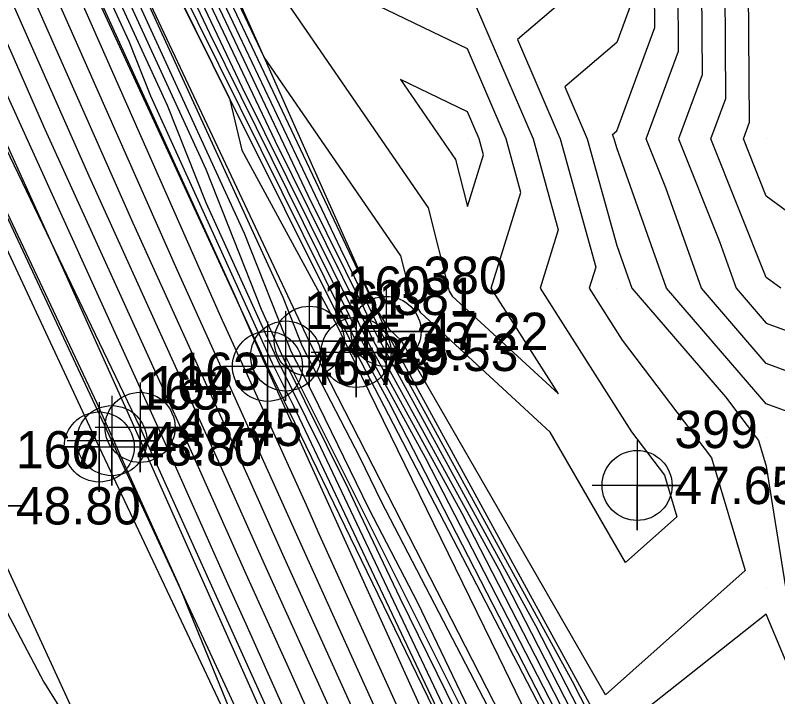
# Model space of a CAD drawing. Extents: x 2090860 to 2091277, y 159470 to 160080.
# Drawn here: x 2091119.7 to 2091170.8, y 159632.7 to 159678.3 of the extents above; entities that cross this region are included whole.
import ezdxf

# ---------------------------------------------------------------- set-up
doc = ezdxf.new("R2010")
doc.units = 0
for name, color, linetype in [('DTM Contours Major', 7, 'Continuous'), ('DTM Contours Minor', 7, 'Continuous'), ('Exist DTM Breakline', 7, 'Continuous'), ('Exist DTM Breakline Cogo Elevation', 7, 'Continuous'), ('Exist DTM Breakline Cogo Number', 7, 'Continuous'), ('Exist DTM Breakline Cogo Point CELL', 7, 'Continuous'), ('Exist DTM Crownline', 7, 'Continuous'), ('Exist DTM Crownline Cogo Elevation', 7, 'Continuous'), ('Exist DTM Crownline Cogo Number', 7, 'Continuous'), ('Exist DTM Crownline Cogo Point CELL', 7, 'Continuous'), ('Exist DTM QL2 LIDAR Elevation Point', 7, 'Continuous'), ('Exist DTM Regular Point CELL', 7, 'Continuous'), ('Exist DTM Regular Point Cogo Elevation', 7, 'Continuous'), ('Exist DTM Regular Point Cogo Number', 7, 'Continuous'), ('Exist Roads EOP', 7, 'Continuous'), ('Exist Roads EOP Cogo Elevation', 7, 'Continuous'), ('Exist Roads EOP Cogo Number', 7, 'Continuous'), ('Exist Roads EOP Cogo Point CELL', 7, 'Continuous'), ('Exist Roads EOT', 7, 'Continuous'), ('Exist Roads EOT Cogo Elevation', 7, 'Continuous'), ('Exist Roads EOT Cogo Number', 7, 'Continuous'), ('Exist Roads EOT Cogo Point CELL', 7, 'Continuous')]:
    doc.layers.add(name, color=color, linetype=linetype)

msp = doc.modelspace()

# ---------------------------------------------------------------- linework, layer by layer
at = {"layer": 'DTM Contours Major'}
for points in [[(2091113.978, 159781.196), (2091107.95, 159774.542), (2091109.45, 159770.226), (2091108.284, 159761.501), (2091106.966, 159748.316), (2091108.177, 159744.971), (2091106.747, 159743.886), (2091107.873, 159737.592), (2091109.304, 159732.696), (2091114.431, 159718.45), (2091115.247, 159716.067), (2091116.563, 159712.414), (2091119.92, 159704.896), (2091128.935, 159685.065), (2091128.953, 159685.024), (2091132.725, 159677.067), (2091142.133, 159658.086), (2091142.373, 159657.575), (2091143.105, 159656.097), (2091147.178, 159648.664), (2091157.027, 159629.517), (2091160.822, 159622.14), (2091162.224, 159619.585), (2091172.872, 159598.824)], [(2091172.606, 159609.793), (2091167.266, 159614.052), (2091165.877, 159617.077), (2091164.245, 159620.259), (2091159.237, 159629.383), (2091158.623, 159630.578), (2091157.028, 159633.678), (2091144.289, 159656.927), (2091144.155, 159657.198), (2091143.409, 159658.787), (2091141.517, 159662.605), (2091130.506, 159685.833), (2091130.452, 159685.953), (2091126.87, 159693.834)], [(2091171.958, 159584.503), (2091159.156, 159611.268), (2091158.366, 159612.924), (2091155.978, 159617.917), (2091145.488, 159639.267), (2091142.826, 159644.878), (2091142.03, 159646.557), (2091137.674, 159655.374), (2091136.215, 159658.575), (2091132.508, 159667.94), (2091125.612, 159682.971)], [(2091165.757, 159588.524), (2091155.652, 159609.466), (2091154.889, 159611.092), (2091152.463, 159616.122), (2091149.484, 159622.796), (2091140.107, 159643.495), (2091139.218, 159645.485), (2091135.295, 159654.14), (2091133.499, 159658.093), (2091123.124, 159681.571)], [(2091170.983, 159660), (2091170, 159660.722), (2091166.303, 159670), (2091167.296, 159672.704), (2091167.247, 159680)], [(2091163.429, 159579.673), (2091153.599, 159600.613), (2091150.617, 159606.792), (2091148.169, 159612.011), (2091147.459, 159613.481), (2091138.047, 159634.57), (2091135.191, 159640.875), (2091131.528, 159649.079), (2091130.314, 159651.757), (2091121.742, 159670.624), (2091117.989, 159679.115)], [(2091160.956, 159679.044), (2091160, 159676.442), (2091156.527, 159673.473), (2091158.023, 159670), (2091160, 159662.853), (2091161.013, 159660), (2091167.276, 159652.724), (2091169.487, 159649.81), (2091170, 159648.096), (2091171.297, 159640)], [(2091150.781, 159670), (2091150, 159671.814), (2091145.512, 159673.979), (2091149.21, 159668.609), (2091150, 159665.461), (2091151.08, 159668.92), (2091150.781, 159670)]]:
    msp.add_lwpolyline(points, dxfattribs=at)
at = {"layer": 'DTM Contours Minor'}
for points in [[(2091113.452, 159782.082), (2091106.971, 159774.929), (2091107.612, 159773.082), (2091107.114, 159769.349), (2091104.896, 159747.166), (2091105.245, 159746.204), (2091104.833, 159745.892), (2091105.157, 159744.081), (2091107.089, 159737.471), (2091114.009, 159718.241), (2091114.505, 159716.794), (2091116.173, 159712.162), (2091118.183, 159707.661), (2091128.555, 159684.843), (2091128.565, 159684.821), (2091130.527, 159680.683), (2091141.814, 159657.91), (2091141.927, 159657.669), (2091142.809, 159655.89), (2091144.716, 159652.41), (2091156.628, 159629.252), (2091161.218, 159620.33), (2091161.719, 159619.417), (2091174.621, 159594.26)], [(2091092.675, 159687.628), (2091098.961, 159674.873), (2091100.257, 159672.453), (2091101.069, 159671.14), (2091105.715, 159663.627), (2091115.58, 159644.724), (2091116.703, 159642.969), (2091121.642, 159633.637), (2091122.802, 159631.775), (2091129.869, 159618.089), (2091132.718, 159622.878), (2091137.14, 159624.41), (2091135.353, 159628.744), (2091131.259, 159638.725), (2091131.05, 159639.235), (2091130.694, 159640.103), (2091126.571, 159649.248), (2091126.304, 159649.847), (2091125.204, 159652.293), (2091113.546, 159676.999), (2091113.443, 159677.236), (2091111.307, 159681.76)], [(2091157.261, 159680), (2091153.346, 159676.654), (2091156.213, 159670), (2091158.588, 159661.412), (2091158.148, 159660), (2091160.356, 159656.534), (2091166.34, 159648.646), (2091168.601, 159641.101), (2091159.236, 159632.792), (2091145.589, 159656.478), (2091144.773, 159657.229), (2091143.784, 159658.844), (2091143.728, 159658.963), (2091143.715, 159658.99), (2091130.894, 159686.036)], [(2091150.165, 159679.835), (2091154.402, 159670), (2091156.086, 159663.914), (2091154.863, 159660), (2091160.988, 159650.39), (2091163.194, 159647.481), (2091164.028, 159644.7), (2091160.575, 159641.636), (2091155.544, 159650.369), (2091146.88, 159658.346), (2091146.247, 159659.38), (2091145.548, 159662.163), (2091136.388, 159675.467), (2091131.282, 159686.238)], [(2091129.729, 159685.429), (2091137.121, 159669.836), (2091142.771, 159658.436), (2091143.264, 159657.386), (2091143.697, 159656.512), (2091152.103, 159641.171), (2091157.825, 159630.047), (2091160.03, 159625.762), (2091163.235, 159619.922), (2091169.375, 159607.95), (2091174.599, 159596.569)], [(2091130.118, 159685.631), (2091139.319, 159666.221), (2091143.09, 159658.612), (2091143.709, 159657.292), (2091143.993, 159656.72), (2091154.566, 159637.424), (2091158.224, 159630.313), (2091159.634, 159627.573), (2091163.74, 159620.091), (2091167.626, 159612.514), (2091170.933, 159605.31)], [(2091171.123, 159603.387), (2091162.729, 159619.754), (2091160.426, 159623.951), (2091157.426, 159629.782), (2091149.641, 159644.917), (2091143.401, 159656.305), (2091142.818, 159657.48), (2091142.452, 159658.261), (2091134.923, 159673.452), (2091129.341, 159685.226)], [(2091128.329, 159684.298), (2091134.074, 159672.707), (2091134.907, 159669.238), (2091141.245, 159657.579), (2091142.079, 159655.819), (2091142.914, 159654.108), (2091152.076, 159635.345), (2091157.313, 159624.61), (2091159.9, 159619.312), (2091161.551, 159616.509), (2091168.282, 159602.906), (2091175.112, 159590.435)], [(2091173.723, 159585.042), (2091166.893, 159599.078), (2091161.009, 159612.222), (2091159.843, 159614.568), (2091157.892, 159618.986), (2091154.934, 159625.148), (2091144.258, 159645.705), (2091142.823, 159648.654), (2091138.936, 159656.155), (2091137.663, 159659.37), (2091126.567, 159683.556)], [(2091172.908, 159584.624), (2091161.198, 159608.686), (2091159.88, 159611.631), (2091156.831, 159617.768), (2091156.621, 159618.241), (2091146.685, 159638.935), (2091143.428, 159645.208), (2091139.631, 159653.008), (2091138.229, 159655.713), (2091135.085, 159663.655), (2091126.089, 159683.263)], [(2091152.592, 159670), (2091150, 159676.016), (2091135.114, 159683.199), (2091147.379, 159665.386), (2091148.781, 159659.799), (2091148.987, 159659.463), (2091156.089, 159652.924), (2091151.579, 159660), (2091153.583, 159666.417), (2091152.592, 159670)], [(2091160.862, 159578.349), (2091151.097, 159599.184), (2091148.077, 159605.5), (2091147.174, 159607.39), (2091144.949, 159612.13), (2091141.732, 159619.248), (2091132.693, 159639.533), (2091131.752, 159641.619), (2091127.777, 159650.544), (2091122.382, 159662.543), (2091115.863, 159676.89), (2091115.422, 159677.888), (2091115.345, 159678.061), (2091113.296, 159682.58)], [(2091170.957, 159583.654), (2091159.144, 159608.415), (2091158.037, 159610.728), (2091155.026, 159617.04), (2091154.862, 159617.384), (2091154.139, 159618.855), (2091141.984, 159644.478), (2091138.346, 159652.145), (2091136.954, 159654.964), (2091128.801, 159672.849), (2091127.352, 159676.51), (2091124.656, 159682.386)], [(2091171.528, 159583.932), (2091165.551, 159596.459), (2091158.597, 159610.998), (2091156.696, 159614.982), (2091155.42, 159617.651), (2091149.814, 159629.061), (2091142.405, 159644.678), (2091140.188, 159649.351), (2091137.314, 159655.169), (2091132.508, 159665.712), (2091129.93, 159672.225), (2091125.134, 159682.678)], [(2091167.322, 159581.737), (2091162.717, 159591.546), (2091154.394, 159608.797), (2091153.209, 159611.322), (2091151.212, 159615.462), (2091146.624, 159625.74), (2091138.878, 159642.84), (2091137.296, 159646.383), (2091134.05, 159653.544), (2091130.56, 159661.226), (2091121.84, 159680.957)], [(2091166.024, 159581.049), (2091159.678, 159594.568), (2091153.135, 159608.129), (2091151.529, 159611.552), (2091149.961, 159614.801), (2091143.765, 159628.683), (2091137.649, 159642.185), (2091135.373, 159647.282), (2091132.805, 159652.949), (2091127.62, 159664.358), (2091120.556, 159680.343)], [(2091168.797, 159585.501), (2091156.911, 159610.135), (2091156.569, 159610.863), (2091153.713, 159616.782), (2091152.343, 159619.853), (2091141.336, 159644.15), (2091141.141, 159644.586), (2091136.54, 159654.736), (2091136.439, 159654.96), (2091134.42, 159659.528), (2091125.094, 159679.986)], [(2091171.655, 159651.655), (2091170, 159652.259), (2091163.337, 159660), (2091160, 159669.398), (2091159.833, 159670), (2091159.707, 159670.293), (2091160, 159670.543), (2091162.541, 159677.459), (2091162.524, 159680)], [(2091173.633, 159653.633), (2091170, 159654.959), (2091165.661, 159660), (2091163.272, 159666.728), (2091161.968, 159670), (2091164.126, 159675.874), (2091164.098, 159680)], [(2091165.673, 159680), (2091165.711, 159674.289), (2091164.136, 159670), (2091166.875, 159663.125), (2091167.985, 159660), (2091170, 159657.659), (2091175.612, 159655.612)], [(2091178.384, 159660), (2091170, 159666.162), (2091168.471, 159670), (2091168.882, 159671.118), (2091168.821, 159680)], [(2091164.726, 159580.361), (2091156.638, 159597.591), (2091151.876, 159607.46), (2091149.849, 159611.781), (2091148.71, 159614.141), (2091140.906, 159631.627), (2091136.42, 159641.53), (2091133.451, 159648.18), (2091131.56, 159652.353), (2091124.681, 159667.491), (2091119.273, 159679.729)], [(2091162.131, 159578.985), (2091150.559, 159603.635), (2091149.359, 159606.123), (2091146.488, 159612.24), (2091146.209, 159612.821), (2091135.187, 159637.514), (2091133.962, 159640.22), (2091129.606, 159649.977), (2091129.069, 159651.161), (2091118.802, 159673.757), (2091116.705, 159678.502)], [(2091173.426, 159630), (2091170, 159638.18), (2091160.501, 159630.672), (2091165.512, 159621.989), (2091177.521, 159622.479), (2091173.426, 159630)]]:
    msp.add_lwpolyline(points, dxfattribs=at)
at = {"layer": 'Exist DTM Breakline'}
for points in [[(2091212.183, 159510.746), (2091191.689, 159549.546), (2091174.865, 159585.627), (2091158.431, 159619.302), (2091139.416, 159656.456), (2091124.853, 159687.366), (2091111.104, 159719.28), (2091102.676, 159740.8), (2091098.872, 159752.926), (2091092.871, 159757.669)], [(2091196.63, 159502.872), (2091177.33, 159544.144), (2091161.139, 159578.46), (2091145.393, 159612.39), (2091128.083, 159650.689), (2091112.842, 159682.377), (2091098.521, 159713.445), (2091088.424, 159738.261), (2091087.489, 159747.73)], [(2091104.06, 159746.702), (2091118.019, 159713.353), (2091131.537, 159686.371), (2091144.554, 159657.113), (2091164.611, 159620.381), (2091178.178, 159588.037), (2091195.659, 159551.391), (2091212.727, 159517.77)], [(2091103.084, 159746.105), (2091115.591, 159711.787), (2091128.144, 159684.602), (2091142.549, 159655.707), (2091161.438, 159619.323), (2091177.759, 159587.787), (2091194.782, 159551.104), (2091211.895, 159517.387)], [(2091206.488, 159507.898), (2091187.957, 159548.134), (2091170.754, 159583.555), (2091154.779, 159617.345), (2091136.615, 159654.772), (2091121.985, 159686.47), (2091108.438, 159717.464), (2091100.122, 159738.875)], [(2091208.294, 159508.466), (2091189.147, 159548.511), (2091172.112, 159584.216), (2091156.469, 159618.152), (2091137.831, 159655.463)]]:
    msp.add_lwpolyline(points, dxfattribs=at)
at = {"layer": 'Exist DTM Breakline Cogo Point CELL'}
for points in [[(2091144.554, 159660.113), (2091144.554, 159654.113), (2091144.554, 159657.113), (2091147.554, 159657.113), (2091141.554, 159657.113)], [(2091139.416, 159659.456), (2091139.416, 159653.456), (2091139.416, 159656.456), (2091142.416, 159656.456), (2091136.416, 159656.456)], [(2091137.831, 159658.463), (2091137.831, 159652.463), (2091137.831, 159655.463), (2091140.831, 159655.463), (2091134.831, 159655.463)], [(2091142.549, 159658.707), (2091142.549, 159652.707), (2091142.549, 159655.707), (2091145.549, 159655.707), (2091139.549, 159655.707)], [(2091136.615, 159657.772), (2091136.615, 159651.772), (2091136.615, 159654.772), (2091139.615, 159654.772), (2091133.615, 159654.772)], [(2091128.083, 159653.689), (2091128.083, 159647.689), (2091128.083, 159650.689), (2091131.083, 159650.689), (2091125.083, 159650.689)]]:
    msp.add_lwpolyline(points, dxfattribs=at)
for centre in [(2091144.554, 159657.113), (2091139.416, 159656.456), (2091137.831, 159655.463), (2091142.549, 159655.707), (2091136.615, 159654.772), (2091128.083, 159650.689)]:
    msp.add_circle(centre, 2.344, dxfattribs=at)
at = {"layer": 'Exist DTM Crownline'}
msp.add_lwpolyline([(2091186.231, 159497.374), (2091150.267, 159573.786), (2091135.077, 159606.786), (2091117.269, 159645.439), (2091102.614, 159676.949), (2091088.105, 159708.377), (2091072.916, 159741.265)], dxfattribs=at)
at = {"layer": 'Exist DTM Crownline Cogo Point CELL'}
msp.add_lwpolyline([(2091117.269, 159648.439), (2091117.269, 159642.439), (2091117.269, 159645.439), (2091120.269, 159645.439), (2091114.269, 159645.439)], dxfattribs=at)
at = {"layer": 'Exist DTM QL2 LIDAR Elevation Point'}
for p, q in [((2091150, 159670), (2091150, 159670)), ((2091160, 159670), (2091160, 159670)), ((2091170, 159670), (2091170, 159670)), ((2091150, 159660), (2091150, 159660)), ((2091160, 159660), (2091160, 159660)), ((2091170, 159660), (2091170, 159660)), ((2091170, 159650), (2091170, 159650)), ((2091170, 159640), (2091170, 159640))]:
    msp.add_line(p, q, dxfattribs=at)
at = {"layer": 'Exist DTM Regular Point CELL'}
msp.add_lwpolyline([(2091161.357, 159649.801), (2091161.357, 159643.801), (2091161.357, 159646.801), (2091164.357, 159646.801), (2091158.357, 159646.801)], dxfattribs=at)
msp.add_circle((2091161.357, 159646.801), 2.344, dxfattribs=at)
at = {"layer": 'Exist Roads EOP'}
msp.add_lwpolyline([(2091195.022, 159502.3), (2091175.816, 159543.301), (2091159.602, 159577.847), (2091143.942, 159611.542), (2091126.198, 159649.797), (2091111.241, 159681.734), (2091096.716, 159712.783), (2091082.116, 159745.373)], dxfattribs=at)
at = {"layer": 'Exist Roads EOP Cogo Point CELL'}
msp.add_lwpolyline([(2091126.198, 159652.797), (2091126.198, 159646.797), (2091126.198, 159649.797), (2091129.198, 159649.797), (2091123.198, 159649.797)], dxfattribs=at)
msp.add_circle((2091126.198, 159649.797), 2.344, dxfattribs=at)
at = {"layer": 'Exist Roads EOT'}
msp.add_lwpolyline([(2091194.37, 159502.018), (2091175.119, 159542.803), (2091158.987, 159577.703), (2091143.368, 159611.224), (2091125.349, 159649.375), (2091110.434, 159681.3), (2091096.012, 159712.514), (2091081.141, 159744.981)], dxfattribs=at)
at = {"layer": 'Exist Roads EOT Cogo Point CELL'}
for points in [[(2091125.349, 159652.375), (2091125.349, 159646.375), (2091125.349, 159649.375), (2091122.349, 159649.375), (2091128.349, 159649.375)], [(2091117.269, 159648.439), (2091117.269, 159642.439), (2091117.269, 159645.439), (2091114.269, 159645.439), (2091120.269, 159645.439)]]:
    msp.add_lwpolyline(points, dxfattribs=at)
msp.add_circle((2091125.349, 159649.375), 2.344, dxfattribs=at)

# ---------------------------------------------------------------- texts
at = {"layer": 'Exist DTM Breakline Cogo Elevation'}
for s, p in [('47.22', (2091147.054, 159655.863)), ('45.33', (2091141.916, 159655.206)), ('45.53', (2091145.049, 159654.457)), ('45.89', (2091140.331, 159654.213)), ('46.73', (2091139.115, 159653.522)), ('48.45', (2091130.583, 159649.439))]:
    msp.add_text(s, height=2.5, dxfattribs=at).set_placement(p)
at = {"layer": 'Exist DTM Breakline Cogo Number'}
for s, p in [('380', (2091147.054, 159659.613)), ('160', (2091141.916, 159658.956)), ('161', (2091140.331, 159657.963)), ('381', (2091145.049, 159658.207)), ('162', (2091139.115, 159657.272)), ('163', (2091130.583, 159653.189))]:
    msp.add_text(s, height=2.5, dxfattribs=at).set_placement(p)
at = {"layer": 'Exist DTM Crownline Cogo Elevation'}
msp.add_text('48.80', height=2.5, dxfattribs=at).set_placement((2091119.769, 159644.189))
at = {"layer": 'Exist DTM Crownline Cogo Number'}
msp.add_text('167', height=2.5, dxfattribs=at).set_placement((2091119.769, 159647.939))
at = {"layer": 'Exist DTM Regular Point Cogo Elevation'}
msp.add_text('47.65', height=2.5, dxfattribs=at).set_placement((2091163.857, 159645.551))
at = {"layer": 'Exist DTM Regular Point Cogo Number'}
msp.add_text('399', height=2.5, dxfattribs=at).set_placement((2091163.857, 159649.301))
at = {"layer": 'Exist Roads EOP Cogo Elevation'}
msp.add_text('48.77', height=2.5, dxfattribs=at).set_placement((2091128.698, 159648.547))
at = {"layer": 'Exist Roads EOP Cogo Number'}
msp.add_text('164', height=2.5, dxfattribs=at).set_placement((2091128.698, 159652.297))
at = {"layer": 'Exist Roads EOT Cogo Elevation'}
for p in [(2091127.849, 159648.125), (2091119.769, 159644.189)]:
    msp.add_text('48.80', height=2.5, dxfattribs=at).set_placement(p)
at = {"layer": 'Exist Roads EOT Cogo Number'}
for s, p in [('165', (2091127.849, 159651.875)), ('166', (2091119.769, 159647.939))]:
    msp.add_text(s, height=2.5, dxfattribs=at).set_placement(p)

doc.saveas('drawing.dxf')
